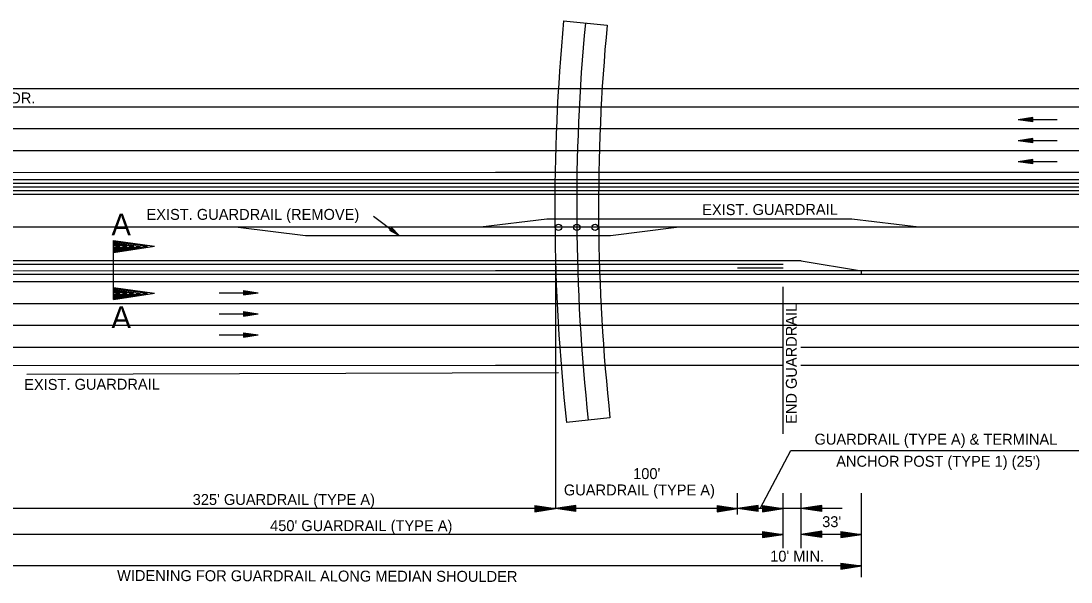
# Model space of a CAD drawing. Extents: x 1373853 to 1374003, y 380191 to 380927.
# Drawn here: x 1373894.8 to 1373952.4, y 380405.1 to 380435.9 of the extents above; entities that cross this region are included whole.
import ezdxf

# ---------------------------------------------------------------- set-up
doc = ezdxf.new("R2010")
doc.units = 0
doc.layers.add('Default', color=7, linetype='Continuous')
doc.layers.add('R_Draft', color=7, linetype='Continuous')

msp = doc.modelspace()

# ---------------------------------------------------------------- linework, layer by layer
at = {"layer": 'Default'}
for p, q in [((1373924.592, 380435.948), (1373926.981, 380435.722)), ((1373979.008, 380432.219), (1373872.226, 380432.215)), ((1373979.008, 380431.219), (1373872.226, 380431.215)), ((1373950.344, 380430.647), (1373949.544, 380430.527)), ((1373951.693, 380430.527), (1373949.544, 380430.527)), ((1373950.344, 380430.407), (1373949.544, 380430.527)), ((1373950.344, 380430.627), (1373949.678, 380430.527)), ((1373950.344, 380430.427), (1373949.678, 380430.527)), ((1373950.344, 380430.607), (1373949.815, 380430.527)), ((1373950.344, 380430.448), (1373949.815, 380430.527)), ((1373950.344, 380430.587), (1373949.949, 380430.527)), ((1373950.344, 380430.468), (1373949.949, 380430.527)), ((1373950.344, 380430.567), (1373950.084, 380430.527)), ((1373950.344, 380430.489), (1373950.084, 380430.527)), ((1373950.344, 380430.546), (1373950.218, 380430.527)), ((1373950.344, 380430.509), (1373950.218, 380430.527)), ((1373950.344, 380430.407), (1373950.344, 380430.647)), ((1373979.008, 380430.019), (1373872.226, 380430.019)), ((1373950.344, 380429.491), (1373949.544, 380429.371)), ((1373951.693, 380429.371), (1373949.544, 380429.371)), ((1373950.344, 380429.251), (1373949.544, 380429.371)), ((1373950.344, 380429.471), (1373949.678, 380429.371)), ((1373950.344, 380429.271), (1373949.678, 380429.371)), ((1373950.344, 380429.45), (1373949.815, 380429.371)), ((1373950.344, 380429.291), (1373949.815, 380429.371)), ((1373950.344, 380429.43), (1373949.949, 380429.371)), ((1373950.344, 380429.311), (1373949.949, 380429.371)), ((1373950.344, 380429.41), (1373950.084, 380429.371)), ((1373950.344, 380429.332), (1373950.084, 380429.371)), ((1373950.344, 380429.389), (1373950.218, 380429.371)), ((1373950.344, 380429.352), (1373950.218, 380429.371)), ((1373950.344, 380429.251), (1373950.344, 380429.491)), ((1373979.008, 380428.819), (1373872.226, 380428.819)), ((1373950.344, 380428.334), (1373949.544, 380428.214)), ((1373951.693, 380428.214), (1373949.544, 380428.214)), ((1373950.344, 380428.094), (1373949.544, 380428.214)), ((1373950.344, 380428.314), (1373949.678, 380428.214)), ((1373950.344, 380428.114), (1373949.678, 380428.214)), ((1373950.344, 380428.293), (1373949.815, 380428.214)), ((1373950.344, 380428.134), (1373949.815, 380428.214)), ((1373950.344, 380428.273), (1373949.949, 380428.214)), ((1373950.344, 380428.154), (1373949.949, 380428.214)), ((1373950.344, 380428.253), (1373950.084, 380428.214)), ((1373950.344, 380428.175), (1373950.084, 380428.214)), ((1373950.344, 380428.233), (1373950.218, 380428.214)), ((1373950.344, 380428.195), (1373950.218, 380428.214)), ((1373950.344, 380428.094), (1373950.344, 380428.334)), ((1373920.856, 380427.617), (1373872.226, 380427.615)), ((1373979.008, 380427.619), (1373920.856, 380427.617)), ((1373920.856, 380427.217), (1373872.226, 380427.215)), ((1373920.856, 380427.017), (1373872.226, 380427.015)), ((1373979.008, 380426.819), (1373872.226, 380426.815)), ((1373979.008, 380427.219), (1373920.856, 380427.217)), ((1373979.008, 380427.019), (1373920.856, 380427.017)), ((1373979.008, 380426.619), (1373872.226, 380426.615)), ((1373979.008, 380426.419), (1373872.226, 380426.415)), ((1373914.163, 380425.223), (1373915.564, 380424.166)), ((1373979.008, 380424.619), (1373872.226, 380424.615)), ((1373915.137, 380424.597), (1373915.029, 380424.452)), ((1373915.029, 380424.452), (1373915.564, 380424.166)), ((1373915.038, 380424.464), (1373915.484, 380424.226)), ((1373915.047, 380424.477), (1373915.401, 380424.288)), ((1373915.056, 380424.489), (1373915.321, 380424.347)), ((1373915.065, 380424.501), (1373915.239, 380424.408)), ((1373915.074, 380424.513), (1373915.159, 380424.468)), ((1373915.091, 380424.536), (1373915.159, 380424.468)), ((1373915.1, 380424.548), (1373915.239, 380424.408)), ((1373915.11, 380424.56), (1373915.321, 380424.347)), ((1373915.118, 380424.572), (1373915.401, 380424.288)), ((1373915.128, 380424.585), (1373915.484, 380424.226)), ((1373915.137, 380424.597), (1373915.564, 380424.166)), ((1373899.879, 380420.642), (1373899.879, 380423.899)), ((1373899.879, 380423.899), (1373902.131, 380423.575)), ((1373899.879, 380423.899), (1373899.884, 380423.224)), ((1373899.88, 380423.842), (1373901.756, 380423.572)), ((1373899.88, 380423.785), (1373901.369, 380423.57)), ((1373899.881, 380423.729), (1373900.994, 380423.568)), ((1373899.881, 380423.67), (1373900.613, 380423.566)), ((1373899.881, 380423.614), (1373900.237, 380423.563)), ((1373899.882, 380423.451), (1373900.613, 380423.566)), ((1373899.882, 380423.508), (1373900.237, 380423.563)), ((1373899.883, 380423.28), (1373901.756, 380423.572)), ((1373899.883, 380423.337), (1373901.369, 380423.57)), ((1373899.883, 380423.393), (1373900.994, 380423.568)), ((1373899.884, 380423.224), (1373902.131, 380423.575)), ((1373921.285, 380422.767), (1373885.64, 380422.766)), ((1373937.64, 380422.768), (1373921.285, 380422.767)), ((1373937.64, 380422.768), (1373940.941, 380422.218)), ((1373920.856, 380422.217), (1373872.226, 380422.215)), ((1373921.285, 380422.567), (1373886.64, 380422.566)), ((1373979.008, 380422.219), (1373920.856, 380422.217)), ((1373936.64, 380422.568), (1373921.285, 380422.567)), ((1373924.14, 380422.567), (1373924.14, 380409.167)), ((1373936.64, 380422.368), (1373934.14, 380422.367)), ((1373920.856, 380422.017), (1373872.226, 380422.015)), ((1373920.856, 380421.617), (1373872.226, 380421.615)), ((1373979.008, 380422.019), (1373920.856, 380422.017)), ((1373979.008, 380421.619), (1373920.856, 380421.617)), ((1373899.875, 380421.317), (1373902.127, 380420.993)), ((1373899.875, 380421.317), (1373899.879, 380420.642)), ((1373899.876, 380421.261), (1373901.752, 380420.991)), ((1373899.876, 380421.204), (1373901.365, 380420.989)), ((1373899.876, 380421.147), (1373900.99, 380420.987)), ((1373899.877, 380421.089), (1373900.609, 380420.984)), ((1373899.877, 380421.033), (1373900.233, 380420.982)), ((1373899.878, 380420.812), (1373900.99, 380420.987)), ((1373899.878, 380420.87), (1373900.609, 380420.984)), ((1373899.878, 380420.927), (1373900.233, 380420.982)), ((1373899.879, 380420.642), (1373902.127, 380420.993)), ((1373899.879, 380420.699), (1373901.752, 380420.991)), ((1373899.879, 380420.756), (1373901.365, 380420.989)), ((1373905.678, 380421.02), (1373907.827, 380421.02)), ((1373907.027, 380421.14), (1373907.827, 380421.02)), ((1373907.027, 380421.14), (1373907.027, 380420.9)), ((1373907.027, 380421.12), (1373907.693, 380421.02)), ((1373907.027, 380421.1), (1373907.556, 380421.02)), ((1373907.027, 380421.08), (1373907.422, 380421.02)), ((1373907.027, 380421.059), (1373907.287, 380421.02)), ((1373907.027, 380421.039), (1373907.153, 380421.02)), ((1373907.027, 380420.9), (1373907.827, 380421.02)), ((1373907.027, 380420.981), (1373907.287, 380421.02)), ((1373907.027, 380420.941), (1373907.556, 380421.02)), ((1373907.027, 380420.92), (1373907.693, 380421.02)), ((1373907.027, 380420.961), (1373907.422, 380421.02)), ((1373907.027, 380421.001), (1373907.153, 380421.02)), ((1373979.008, 380420.419), (1373872.226, 380420.419)), ((1373905.678, 380419.863), (1373907.827, 380419.863)), ((1373907.027, 380419.983), (1373907.827, 380419.863)), ((1373907.027, 380419.983), (1373907.027, 380419.743)), ((1373907.027, 380419.963), (1373907.693, 380419.863)), ((1373907.027, 380419.943), (1373907.556, 380419.863)), ((1373907.027, 380419.923), (1373907.422, 380419.863)), ((1373907.027, 380419.902), (1373907.287, 380419.863)), ((1373907.027, 380419.882), (1373907.153, 380419.863)), ((1373907.027, 380419.743), (1373907.827, 380419.863)), ((1373907.027, 380419.824), (1373907.287, 380419.863)), ((1373907.027, 380419.784), (1373907.556, 380419.863)), ((1373907.027, 380419.763), (1373907.693, 380419.863)), ((1373907.027, 380419.804), (1373907.422, 380419.863)), ((1373907.027, 380419.845), (1373907.153, 380419.863)), ((1373979.008, 380419.219), (1373872.226, 380419.219)), ((1373905.678, 380418.707), (1373907.827, 380418.707)), ((1373907.027, 380418.827), (1373907.827, 380418.707)), ((1373907.027, 380418.827), (1373907.027, 380418.587)), ((1373907.027, 380418.807), (1373907.693, 380418.707)), ((1373907.027, 380418.786), (1373907.556, 380418.707)), ((1373907.027, 380418.766), (1373907.422, 380418.707)), ((1373907.027, 380418.745), (1373907.287, 380418.707)), ((1373907.027, 380418.725), (1373907.153, 380418.707)), ((1373907.027, 380418.587), (1373907.827, 380418.707)), ((1373907.027, 380418.667), (1373907.287, 380418.707)), ((1373907.027, 380418.627), (1373907.556, 380418.707)), ((1373907.027, 380418.607), (1373907.693, 380418.707)), ((1373907.027, 380418.647), (1373907.422, 380418.707)), ((1373907.027, 380418.688), (1373907.153, 380418.707)), ((1373920.856, 380418.017), (1373887.665, 380418.016)), ((1373936.64, 380418.018), (1373920.856, 380418.017)), ((1373979.008, 380418.019), (1373937.618, 380418.018)), ((1373920.856, 380417.017), (1373887.665, 380417.016)), ((1373936.64, 380417.018), (1373920.856, 380417.017)), ((1373979.008, 380417.019), (1373937.618, 380417.018)), ((1373895.12, 380416.555), (1373924.315, 380416.64)), ((1373927.138, 380414.158), (1373924.752, 380413.898)), ((1373934.14, 380408.835), (1373934.14, 380410.02)), ((1373936.64, 380406.995), (1373936.64, 380410.02)), ((1373937.64, 380406.995), (1373937.64, 380410.02)), ((1373940.941, 380405.394), (1373940.941, 380410.02)), ((1373924.14, 380409.167), (1373891.64, 380409.167)), ((1373923.014, 380409.329), (1373924.14, 380409.167)), ((1373923.014, 380409.329), (1373923.017, 380408.992)), ((1373923.015, 380409.301), (1373923.953, 380409.166)), ((1373923.015, 380409.272), (1373923.759, 380409.165)), ((1373923.015, 380409.244), (1373923.572, 380409.164)), ((1373923.015, 380409.215), (1373923.381, 380409.163)), ((1373923.015, 380409.187), (1373923.193, 380409.162)), ((1373923.016, 380409.02), (1373923.953, 380409.166)), ((1373923.016, 380409.049), (1373923.759, 380409.165)), ((1373923.016, 380409.077), (1373923.572, 380409.164)), ((1373923.016, 380409.105), (1373923.381, 380409.163)), ((1373923.016, 380409.134), (1373923.193, 380409.162)), ((1373923.017, 380408.992), (1373924.14, 380409.167)), ((1373925.264, 380409.343), (1373924.14, 380409.167)), ((1373934.14, 380409.167), (1373924.14, 380409.167)), ((1373925.266, 380409.005), (1373924.14, 380409.167)), ((1373925.265, 380409.315), (1373924.328, 380409.168)), ((1373925.266, 380409.033), (1373924.328, 380409.168)), ((1373925.265, 380409.286), (1373924.522, 380409.17)), ((1373925.266, 380409.062), (1373924.522, 380409.17)), ((1373925.265, 380409.258), (1373924.709, 380409.171)), ((1373925.266, 380409.09), (1373924.709, 380409.171)), ((1373925.265, 380409.229), (1373924.9, 380409.172)), ((1373925.266, 380409.119), (1373924.9, 380409.172)), ((1373925.265, 380409.2), (1373925.088, 380409.173)), ((1373925.266, 380409.148), (1373925.088, 380409.173)), ((1373925.266, 380409.005), (1373925.264, 380409.343)), ((1373933.014, 380409.329), (1373934.14, 380409.167)), ((1373933.014, 380409.329), (1373933.016, 380408.992)), ((1373933.015, 380409.301), (1373933.952, 380409.166)), ((1373933.015, 380409.272), (1373933.759, 380409.165)), ((1373933.015, 380409.244), (1373933.572, 380409.164)), ((1373933.015, 380409.215), (1373933.381, 380409.163)), ((1373933.015, 380409.187), (1373933.193, 380409.162)), ((1373933.016, 380408.992), (1373934.14, 380409.167)), ((1373933.016, 380409.02), (1373933.952, 380409.166)), ((1373933.016, 380409.048), (1373933.759, 380409.165)), ((1373933.016, 380409.077), (1373933.572, 380409.164)), ((1373933.016, 380409.105), (1373933.381, 380409.163)), ((1373933.016, 380409.134), (1373933.193, 380409.162)), ((1373935.264, 380409.343), (1373934.14, 380409.167)), ((1373936.64, 380409.167), (1373934.14, 380409.167)), ((1373935.266, 380409.005), (1373934.14, 380409.167)), ((1373935.264, 380409.315), (1373934.328, 380409.168)), ((1373935.266, 380409.033), (1373934.328, 380409.168)), ((1373935.265, 380409.286), (1373934.522, 380409.17)), ((1373935.266, 380409.062), (1373934.522, 380409.17)), ((1373935.265, 380409.258), (1373934.709, 380409.171)), ((1373935.266, 380409.09), (1373934.709, 380409.171)), ((1373935.265, 380409.229), (1373934.9, 380409.172)), ((1373935.266, 380409.119), (1373934.9, 380409.172)), ((1373935.265, 380409.2), (1373935.088, 380409.173)), ((1373935.265, 380409.148), (1373935.088, 380409.173)), ((1373935.266, 380409.005), (1373935.264, 380409.343)), ((1373935.514, 380409.329), (1373936.64, 380409.167)), ((1373935.514, 380409.329), (1373935.516, 380408.992)), ((1373935.514, 380409.301), (1373936.452, 380409.166)), ((1373935.515, 380409.272), (1373936.259, 380409.165)), ((1373935.515, 380409.244), (1373936.072, 380409.164)), ((1373935.515, 380409.215), (1373935.881, 380409.163)), ((1373935.515, 380409.187), (1373935.693, 380409.162)), ((1373935.516, 380408.992), (1373936.64, 380409.167)), ((1373935.516, 380409.02), (1373936.452, 380409.166)), ((1373935.516, 380409.048), (1373936.259, 380409.165)), ((1373935.516, 380409.077), (1373936.072, 380409.164)), ((1373935.516, 380409.105), (1373935.881, 380409.163)), ((1373935.516, 380409.134), (1373935.693, 380409.162)), ((1373937.64, 380409.167), (1373936.64, 380409.167)), ((1373939.874, 380409.167), (1373937.374, 380409.167)), ((1373938.764, 380409.343), (1373937.64, 380409.167)), ((1373938.766, 380409.005), (1373937.64, 380409.167)), ((1373938.764, 380409.315), (1373937.828, 380409.168)), ((1373938.766, 380409.033), (1373937.828, 380409.168)), ((1373938.765, 380409.286), (1373938.022, 380409.17)), ((1373938.766, 380409.062), (1373938.022, 380409.17)), ((1373938.765, 380409.258), (1373938.209, 380409.171)), ((1373938.766, 380409.09), (1373938.209, 380409.171)), ((1373938.765, 380409.229), (1373938.4, 380409.172)), ((1373938.766, 380409.119), (1373938.4, 380409.172)), ((1373938.765, 380409.2), (1373938.588, 380409.173)), ((1373938.765, 380409.148), (1373938.588, 380409.173)), ((1373938.766, 380409.005), (1373938.764, 380409.343)), ((1373936.64, 380407.747), (1373891.64, 380407.747)), ((1373935.514, 380407.909), (1373936.64, 380407.747)), ((1373935.514, 380407.909), (1373935.516, 380407.572)), ((1373935.514, 380407.881), (1373936.452, 380407.746)), ((1373935.515, 380407.853), (1373936.259, 380407.745)), ((1373935.515, 380407.824), (1373936.072, 380407.744)), ((1373935.515, 380407.795), (1373935.881, 380407.743)), ((1373935.515, 380407.767), (1373935.693, 380407.742)), ((1373935.516, 380407.572), (1373936.64, 380407.747)), ((1373935.516, 380407.6), (1373936.452, 380407.746)), ((1373935.516, 380407.629), (1373936.259, 380407.745)), ((1373935.516, 380407.657), (1373936.072, 380407.744)), ((1373935.516, 380407.685), (1373935.881, 380407.743)), ((1373935.516, 380407.714), (1373935.693, 380407.742)), ((1373938.764, 380407.923), (1373937.64, 380407.747)), ((1373938.764, 380407.923), (1373937.64, 380407.747)), ((1373938.766, 380407.585), (1373937.64, 380407.747)), ((1373940.941, 380407.747), (1373937.64, 380407.747)), ((1373938.766, 380407.585), (1373937.64, 380407.747)), ((1373938.764, 380407.895), (1373937.828, 380407.749)), ((1373938.764, 380407.895), (1373937.828, 380407.749)), ((1373938.766, 380407.614), (1373937.828, 380407.749)), ((1373938.766, 380407.614), (1373937.828, 380407.749)), ((1373938.765, 380407.866), (1373938.022, 380407.75)), ((1373938.765, 380407.866), (1373938.022, 380407.75)), ((1373938.766, 380407.642), (1373938.022, 380407.75)), ((1373938.766, 380407.642), (1373938.022, 380407.75)), ((1373938.765, 380407.838), (1373938.209, 380407.751)), ((1373938.765, 380407.838), (1373938.209, 380407.751)), ((1373938.766, 380407.67), (1373938.209, 380407.751)), ((1373938.766, 380407.67), (1373938.209, 380407.751)), ((1373938.765, 380407.809), (1373938.4, 380407.752)), ((1373938.765, 380407.809), (1373938.4, 380407.752)), ((1373938.766, 380407.7), (1373938.4, 380407.752)), ((1373938.766, 380407.7), (1373938.4, 380407.752)), ((1373938.765, 380407.781), (1373938.588, 380407.753)), ((1373938.765, 380407.781), (1373938.588, 380407.753)), ((1373938.765, 380407.728), (1373938.588, 380407.753)), ((1373938.765, 380407.728), (1373938.588, 380407.753)), ((1373938.766, 380407.585), (1373938.764, 380407.923)), ((1373938.766, 380407.585), (1373938.764, 380407.923)), ((1373939.815, 380407.909), (1373940.941, 380407.747)), ((1373939.815, 380407.909), (1373939.817, 380407.572)), ((1373939.815, 380407.881), (1373940.753, 380407.746)), ((1373939.816, 380407.853), (1373940.56, 380407.745)), ((1373939.816, 380407.824), (1373940.373, 380407.744)), ((1373939.816, 380407.795), (1373940.182, 380407.743)), ((1373939.816, 380407.767), (1373939.994, 380407.742)), ((1373939.816, 380407.714), (1373939.994, 380407.742)), ((1373939.817, 380407.572), (1373940.941, 380407.747)), ((1373939.817, 380407.6), (1373940.753, 380407.746)), ((1373939.817, 380407.629), (1373940.56, 380407.745)), ((1373939.817, 380407.657), (1373940.373, 380407.744)), ((1373939.817, 380407.685), (1373940.182, 380407.743)), ((1373924.14, 380406.015), (1373882.34, 380406.015)), ((1373940.941, 380406.015), (1373924.14, 380406.015)), ((1373939.815, 380406.177), (1373940.941, 380406.015)), ((1373939.815, 380406.177), (1373939.817, 380405.839)), ((1373939.815, 380406.149), (1373940.753, 380406.014)), ((1373939.816, 380406.12), (1373940.56, 380406.012)), ((1373939.816, 380406.092), (1373940.373, 380406.011)), ((1373939.816, 380406.062), (1373940.182, 380406.01)), ((1373939.816, 380406.034), (1373939.994, 380406.009)), ((1373939.816, 380405.981), (1373939.994, 380406.009)), ((1373939.817, 380405.839), (1373940.941, 380406.015)), ((1373939.817, 380405.867), (1373940.753, 380406.014)), ((1373939.817, 380405.896), (1373940.56, 380406.012)), ((1373939.817, 380405.924), (1373940.373, 380406.011)), ((1373939.817, 380405.953), (1373940.182, 380406.01))]:
    msp.add_line(p, q, dxfattribs=at)
for points in [[(1373944.1, 380424.619), (1373940.405, 380425.071), (1373923.662, 380425.071), (1373920.036, 380424.619)], [(1373906.731, 380424.617), (1373910.426, 380424.165), (1373927.169, 380424.165), (1373930.796, 380424.617)], [(1373935.39, 380409.167), (1373937.062, 380412.358), (1373937.062, 380412.358), (1373954.591, 380412.358)]]:
    msp.add_lwpolyline(points, dxfattribs=at)
for centre in [(1373924.315, 380424.617), (1373925.315, 380424.617), (1373926.315, 380424.617)]:
    msp.add_circle(centre, 0.175, dxfattribs=at)
for radius in [108.873, 107.673, 106.473]:
    msp.add_arc((1374032.982, 380425.712), radius, 174.60541, 186.22958, dxfattribs=at)
at = {"layer": 'R_Draft'}
for p, q in [((1373940.941, 380422.018), (1373940.941, 380422.218)), ((1373936.64, 380413.273), (1373936.64, 380421.351))]:
    msp.add_line(p, q, dxfattribs=at)

# ---------------------------------------------------------------- texts
at = {"layer": 'Default'}
for s, rotation, p in [("EXIST. 10' SHLDR.", 359.99992, (1373888.623, 380431.421)), ('EXIST. GUARDRAIL (REMOVE)', 359.99992, (1373901.695, 380425.025)), ('EXIST. GUARDRAIL', 0.16796, (1373932.2, 380425.283)), ('EXIST. GUARDRAIL', 0.16796, (1373894.983, 380415.682)), ('GUARDRAIL (TYPE A) & TERMINAL', 359.97706, (1373938.364, 380412.679)), ("ANCHOR POST (TYPE 1) (25')", 359.97706, (1373939.555, 380411.466)), ("100'", 359.97706, (1373928.408, 380410.789)), ('GUARDRAIL (TYPE A)', 359.97706, (1373924.605, 380409.891)), ("325' GUARDRAIL (TYPE A)", 359.99992, (1373904.23, 380409.366)), ("450' GUARDRAIL (TYPE A)", 359.97706, (1373908.48, 380407.93)), ("33'", 359.99992, (1373938.784, 380408.148)), ("10' MIN.", 359.99992, (1373935.93, 380406.253)), ('WIDENING FOR GUARDRAIL ALONG MEDIAN SHOULDER', 359.85643, (1373900.079, 380405.192))]:
    msp.add_text(s, height=0.6, rotation=rotation, dxfattribs=at).set_placement(p)
for p in [(1373899.771, 380424.167), (1373899.771, 380419.079)]:
    msp.add_text('A', height=1.2, dxfattribs=at).set_placement(p)
at = {"layer": 'R_Draft'}
msp.add_text('END GUARDRAIL', height=0.6, rotation=90.00191, dxfattribs=at).set_placement((1373937.393, 380413.817))

doc.saveas('drawing.dxf')
